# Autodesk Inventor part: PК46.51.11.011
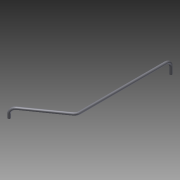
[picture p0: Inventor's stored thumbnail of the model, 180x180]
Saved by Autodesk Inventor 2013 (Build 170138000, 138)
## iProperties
Shininess: 64.0
Length Units: 11269
Angle Units: 11279
Time Units: 11290
Mass Units: 11283
Length Display Precision: 3
Angle Display Precision: 2
Compacted: True
Part Number: PК46.51.11.011
Document SubType Name: Modeling
Created: 2004-12
Material: Steel, Mild
Designer: =<Author>
Manufacturer: Standard
Standards Organization: Custom
Description: handrail
Density: 7.86 g/cm^3
Mass: 2164.05 g
Surface Area: 2206.13 cm^2
Volume: 275.325 cm^3
Density: 0.0
Volumn: 0.0
Area: 0.0
PropertySet Name: Model Information
Control State: 0
Master: False
Checked Out: False
Checked Out Date: 2008-10-15
Last Check In Date: 2008-10-15
d0: 870.000 mm
d1: 425.000 mm
d2: 125.00 deg
d3: 25.000 mm
d4: 20.000 mm
d5: 0.00 deg
d6: 50.000 mm
d7: 50.000 mm
d8: 120.000 mm
d9: 0.00 deg
d10: 90.00 deg
d11: 50.000 mm
d12: 90.000 mm
d13: 0.00 deg
Author: PVitaliy
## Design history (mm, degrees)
node "РабПлоскость1"
feature "Сдвиг1" dims angle "d5" = 0 deg
feature "Сдвиг2" dims angle "d9" = 0 deg
node "РабОсь2"
node "РабПлоскость2"
feature "Сдвиг3" dims angle "d13" = 0 deg
body "Solid1"
sketch "Эскиз1"
  geometry: L1 (0, 26.028)-(0, 870); L2 (-21.321, -14.929)-(-348.14, -243.77); A1 r 50 centre (-50, 26.028) between (-21.321, -14.929) and (0, 26.028); 1 further point
  constraints: 4 end point, 2 point on circle, 2 point on line, 2 tangent, 1 centre point, 1 vertical, 1 other
  dimensions: "d0" = 870 distance of point (0, 0) L1.end; "d1" = 425 distance of point (0, 0) L2.end; "d2" = 125 deg angle of L2 L1; "d6" = 50 radius of A1
sketch "Эскиз2"
  geometry: C1 r 10 at (0, 0); C2 r 12.5 at (0, 0); 1 further point
  constraints: 2 centre point, 2 coincident
  dimensions: "d3" = 25 diameter of C2; "d4" = 20 diameter of C1
sketch "Эскиз3"
  geometry: C1 r 10 at (0, 0) reference; C2 r 12.5 at (0, 0) reference
sketch "Эскиз4"
  geometry: L1 (870, 12.5)-(870, -12.5) reference; L2 (920, -120)-(920, -50); A1 r 50 centre (870, -50) between (920, -50) and (870, 0)
  constraints: 2 end point, 2 point on circle, 1 centre point, 1 midpoint, 1 parallel, 1 point on line, 1 tangent
  dimensions: "d7" = 50 radius of A1; "d8" = 120 vertical distance of L2.start A1.end
sketch "Эскиз5"
  geometry: L1 (398.972, 12.5)-(398.972, -12.5) reference; L2 (448.972, -50)-(448.972, -90); A1 r 50 centre (398.972, -50) between (448.972, -50) and (398.972, 0)
  constraints: 2 end point, 2 point on circle, 1 centre point, 1 midpoint, 1 parallel, 1 point on line, 1 tangent
  dimensions: "d11" = 50 radius of A1; "d12" = 90 vertical distance of L2.end A1.end
sketch "Эскиз6"
  geometry: C1 r 10 at (0, 0) reference; C2 r 12.5 at (0, 0) reference
other parameters: "d10" = 90 deg
